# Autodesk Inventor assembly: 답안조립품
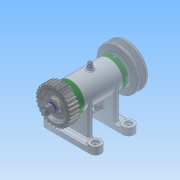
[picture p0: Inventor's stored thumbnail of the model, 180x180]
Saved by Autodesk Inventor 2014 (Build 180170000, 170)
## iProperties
Created: 2015-11
Part Number: 답안조립품
Document SubType Name: Assembly
Designer: net
Author: net
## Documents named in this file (16)
- C:\Users\net\Desktop\451109V1016\답안조립품.iam
- C:\Users\net\Desktop\451109V1016\본체.ipt
- C:\Users\net\Desktop\451109V1016\V벨트풀리.ipt
- C:\Users\net\Desktop\451109V1016\베어링 15 x 32 x 9.ipt
- C:\Users\net\Desktop\451109V1016\스퍼기어.ipt
- C:\Users\net\Desktop\451109V1016\스프링와셔 8.ipt
- C:\Users\net\Desktop\451109V1016\키 3 x 3 x 12.ipt
- C:\Users\net\Desktop\451109V1016\커버.ipt
- C:\Users\net\Desktop\451109V1016\축.ipt
- C:\Users\net\Desktop\451109V1016\오일 실 15 25 7.ipt
- C:\Users\net\Desktop\451109V1016\볼트 M4 x 12.ipt
- C:\Users\net\Desktop\451109V1016\너트 M 8.ipt
- C:\Users\net\Desktop\451109V1016\니플 M 6 x 0.75.ipt
- C:\Users\net\Desktop\451109V1016\와셔 6x11.5.ipt
- C:\Users\net\Desktop\451109V1016\와셔 8x17.ipt
- C:\Users\net\Desktop\451109V1016\볼트 M 6 x 8.ipt
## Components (15 placed, 3 different names)
1. V벨트풀리:1 — 각도:1
2. KS B 2023 6002 - 15 x 32 x 9:1
3. KS B 2023 6002 - 15 x 32 x 9:2
4. ISO 4762 M4 x 12:2
5. ISO 4762 M4 x 12:3
6. ISO 4762 M4 x 12:4
7. ISO 4762 M4 x 12:5
8. ISO 4762 M4 x 12:6
9. ISO 4762 M4 x 12:7
10. ISO 4762 M4 x 12:8
11. ISO 4762 M4 x 12:9
12. ISO 4762 M4 x 12:1
13. ISO 4762 M4 x 12:10
14. ISO 4762 M4 x 12:11
15. ISO 4762 M4 x 12:12
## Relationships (1: Angle 1)
- 각도:1 [Angle]: V벨트풀리:1
